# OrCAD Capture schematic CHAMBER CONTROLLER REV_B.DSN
size C; title: chamber controller; rev: B
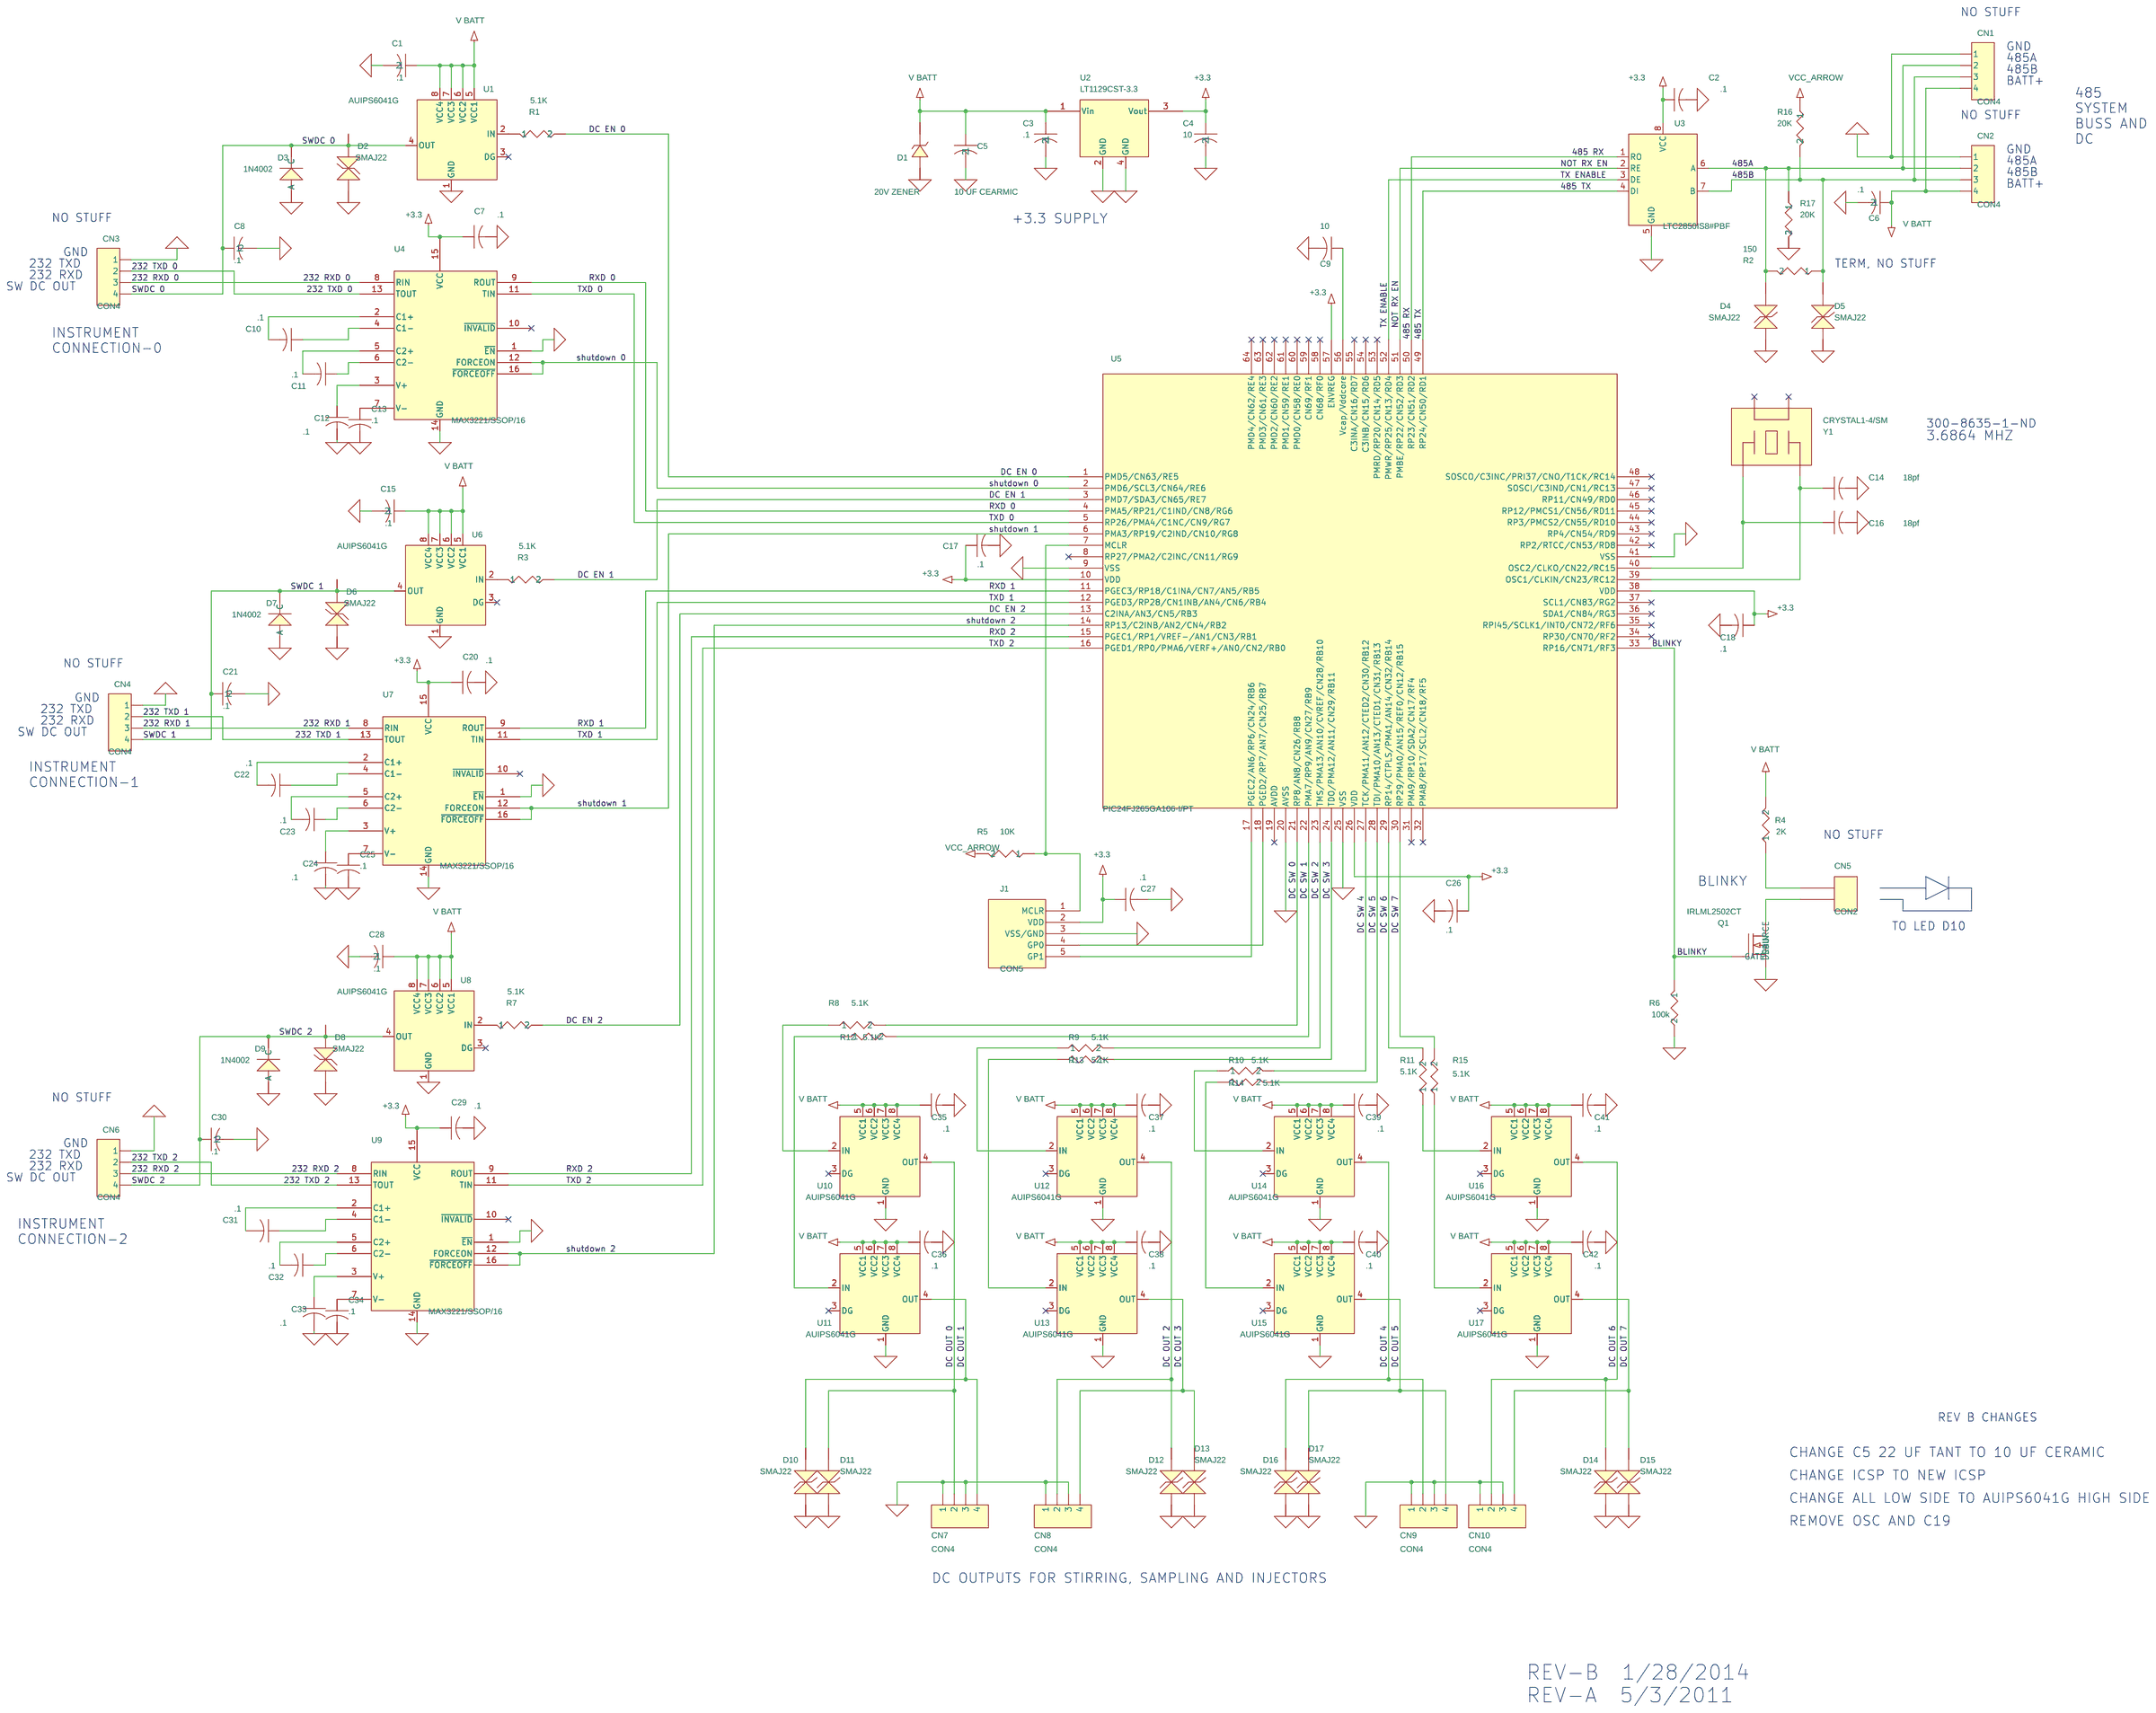
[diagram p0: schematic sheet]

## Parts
C1  .1  [SM/C_0805]
C2  .1  [SM/C_0805]
C3  .1  [SM/C_0805]
C4  10  [SM/C_1210]
C5  10 UF CEARMIC  [SM/CT_7343_12]
C6  .1  [SM/C_0805]
C7  .1  [SM/C_0805]
C8  .1  [SM/C_0805]
C9  10  [SM/C_0805]
C10  .1  [SM/C_0805]
C11  .1  [SM/C_0805]
C12  .1  [SM/C_0805]
C13  .1  [SM/C_0805]
C14  18pf  [SM/C_0805]
C15  .1  [SM/C_0805]
C16  18pf  [SM/C_0805]
C17  .1  [SM/C_0805]
C18  .1  [SM/C_0805]
C20  .1  [SM/C_0805]
C21  .1  [SM/C_0805]
C22  .1  [SM/C_0805]
C23  .1  [SM/C_0805]
C24  .1  [SM/C_0805]
C25  .1  [SM/C_0805]
C26  .1  [SM/C_0805]
C27  .1  [SM/C_0805]
C28  .1  [SM/C_0805]
C29  .1  [SM/C_0805]
C30  .1  [SM/C_0805]
C31  .1  [SM/C_0805]
C32  .1  [SM/C_0805]
C33  .1  [SM/C_0805]
C34  .1  [SM/C_0805]
C35  .1  [SM/C_0805]
C36  .1  [SM/C_0805]
C37  .1  [SM/C_0805]
C38  .1  [SM/C_0805]
C39  .1  [SM/C_0805]
C40  .1  [SM/C_0805]
C41  .1  [SM/C_0805]
C42  .1  [SM/C_0805]
CN1  CON4  [BLKCON.156/VH/TM1SQS/W.156/4]
CN2  CON4  [BLKCON.156/VH/TM1SQS/W.156/4]
CN3  CON4  [BLKCON.156/VH/TM1SQS/W.156/4]
CN4  CON4  [BLKCON.156/VH/TM1SQS/W.156/4]
CN5  CON2  [BLKCON.156/VH/TM1SQS/W.156/2]
CN6  CON4  [BLKCON.156/VH/TM1SQS/W.156/4]
CN7  CON4  [BLKCON.156/VH/TM1SQS/W.156/4]
CN8  CON4  [BLKCON.156/VH/TM1SQS/W.156/4]
CN9  CON4  [BLKCON.156/VH/TM1SQS/W.156/4]
CN10  CON4  [BLKCON.156/VH/TM1SQS/W.156/4]
D1  20V ZENER  [SM/DO213AB_12]
D2  SMAJ22  [SM/R_2010]
D3  1N4002  [SM/D_MLL41]
D4  SMAJ22  [SM/R_2010]
D5  SMAJ22  [SM/R_2010]
D6  SMAJ22  [SM/R_2010]
D7  1N4002  [SM/D_MLL41]
D8  SMAJ22  [SM/R_2010]
D9  1N4002  [SM/D_MLL41]
D10  SMAJ22  [SM/R_2010]
D11  SMAJ22  [SM/R_2010]
D12  SMAJ22  [SM/R_2010]
D13  SMAJ22  [SM/R_2010]
D14  SMAJ22  [SM/R_2010]
D15  SMAJ22  [SM/R_2010]
D16  SMAJ22  [SM/R_2010]
D17  SMAJ22  [SM/R_2010]
J1  CON5  [BLKCON.100/VH/TM1SQS/W.100/5]
Q1  IRLML2502CT  [SM/SOT23_123]
R1  5.1K  [SM/C_0805]
R2  150  [SM/C_0805]
R3  5.1K  [SM/C_0805]
R4  2K  [SM/C_0805]
R5  10K  [SM/C_0805]
R6  100k  [SM/C_0805]
R7  5.1K  [SM/C_0805]
R8  5.1K  [SM/C_0805]
R9  5.1K  [SM/C_0805]
R10  5.1K  [SM/C_0805]
R11  5.1K  [SM/C_0805]
R12  5.1K  [SM/C_0805]
R13  5.1K  [SM/C_0805]
R14  5.1K  [SM/C_0805]
R15  5.1K  [SM/C_0805]
R16  20K  [SM/C_0805]
R17  20K  [SM/C_0805]
U1  AUIPS6041G  [SOG.050/8/WG.244/L.175]
U2  LT1129CST-3.3  [SM/SOT223_1234]
U3  LTC2850IS8#PBF  [SOG.050/8/WG.244/L.200]
U4  MAX3221/SSOP/16  [SOG.65M/16/WG8.20/L6.35]
U5  PIC24FJ265GA106-I/PT  [QUAD.50M/64/WG11]
U6  AUIPS6041G  [SOG.050/8/WG.244/L.175]
U7  MAX3221/SSOP/16  [SOG.65M/16/WG8.20/L6.35]
U8  AUIPS6041G  [SOG.050/8/WG.244/L.175]
U9  MAX3221/SSOP/16  [SOG.65M/16/WG8.20/L6.35]
U10  AUIPS6041G  [SOG.050/8/WG.244/L.175]
U11  AUIPS6041G  [SOG.050/8/WG.244/L.175]
U12  AUIPS6041G  [SOG.050/8/WG.244/L.175]
U13  AUIPS6041G  [SOG.050/8/WG.244/L.175]
U14  AUIPS6041G  [SOG.050/8/WG.244/L.175]
U15  AUIPS6041G  [SOG.050/8/WG.244/L.175]
U16  AUIPS6041G  [SOG.050/8/WG.244/L.175]
U17  AUIPS6041G  [SOG.050/8/WG.244/L.175]
Y1  CRYSTAL1-4/SM  [SMXTAL_2]

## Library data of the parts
C1 = CAP
C2 C7 C9-C14 C16-C18 C20 C22-C27 C29 C31-C42 = CAPACITOR
C3 = CAP_8
C4 = CAP_6
C5 = CAP_2
C6 = CAP_3
C8 = CAP_5
C15 = CAP_7
C21 = CAP_9
C28 = CAP_4
C30 = CAP_1
CN1 = CON4_7
CN2 = CON4_4
CN3 = CON4
CN4 = CON4_3
CN5 = CON2
CN6 = CON4_6
CN7 = CON4_2
CN8 = CON4_8
CN9 = CON4_5
CN10 = CON4_1
D1 = DIODE_ZENER_0
D2 D4-D6 D8 D10-D17 = TRANZORB_1
D3 = DIODE_0_2
D7 = DIODE_0
D9 = DIODE_0_1
J1 = CON5_0
Q1 = MOSFET_N_1
R1 = RESISTOR_16
R2 = RESISTOR_3
R3 = RESISTOR_14
R4 = RESISTOR_13
R5 = RESISTOR_9
R6 = RESISTOR_15
R7 = RESISTOR_10
R8 = RESISTOR_5
R9 = RESISTOR
R10 = RESISTOR_6
R11 = RESISTOR_2
R12 = RESISTOR_7
R13 = RESISTOR_1
R14 = RESISTOR_12
R15 = RESISTOR_8
R16 = RESISTOR_4
R17 = RESISTOR_11
U1 U6 U8 U10-U17 = IPS6041GPbF_0
U2 = 78XX_SM_0
U3 = SN65LVDS179_SO_2
U4 U7 U9 = MAX3221_SO_0
U5 = PIC24FJ256GA110_0
Y1 = CRYSTAL1-4_SM_0

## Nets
GND_SIGNAL: C1.2 C2.2 C3.2 C4.2 C5.2 C6.2 C7.2 C8.2 C9.2 C12.2 C13.2 C14.2 C15.2 C16.2 C17.2 C18.2 C20.2 C21.2 C24.2 C25.2 C26.2 C27.2 C28.2 C29.2 C30.2 C33.2 C34.2 C35.2 C36.2 C37.2 C38.2 C39.2 C40.2 C41.2 C42.2 CN1.1 CN2.1 CN3.1 CN4.1 CN6.1 CN7.1 CN7.3 CN8.1 CN8.3 CN9.1 CN9.3 CN10.1 CN10.3 D1.2(ANODE) D2.1 D3.A D4.1 D5.1 D6.1 D7.A D8.1 D9.A D10.1 D11.1 D12.1 D13.1 D14.1 D15.1 D16.1 D17.1 J1.3(VSS/GND) Q1.2(SOURCE) R6.2 R17.2 U1.1(GND) U2.2(GND) U2.4(GND) U3.5(GND) U4.1(~{EN}) U4.14(GND) U5.9(VSS) U5.20(AVSS) U5.25(VSS) U5.41(VSS) U6.1(GND) U7.1(~{EN}) U7.14(GND) U8.1(GND) U9.1(~{EN}) U9.14(GND) U10.1(GND) U11.1(GND) U12.1(GND) U13.1(GND) U14.1(GND) U15.1(GND) U16.1(GND) U17.1(GND)
232 RXD 0: CN3.3 U4.8(RIN)
232 RXD 1: CN4.3 U7.8(RIN)
232 RXD 2: CN6.3 U9.8(RIN)
232 TXD 0: CN3.2 U4.13(TOUT)
232 TXD 1: CN4.2 U7.13(TOUT)
232 TXD 2: CN6.2 U9.13(TOUT)
485 RX: U3.1(RO) U5.50(RP23/CN51/RD2)
485 TX: U3.4(DI) U5.49(RP24/CN50/RD1)
485A: CN1.2 CN2.2 D4.2 R2.2 R17.1 U3.6(A)
485B: CN1.3 CN2.3 D5.2 R2.1 R16.2 U3.7(B)
+3.3: C2.1 C4.1 C7.1 C17.1 C18.1 C20.1 C26.1 C27.1 C29.1 J1.2(VDD) R5.2 R16.1 U2.3(Vout) U3.8(VCC) U4.15(VCC) U5.10(VDD) U5.26(VDD) U5.38(VDD) U5.57(ENVREG) U7.15(VCC) U9.15(VCC)
BLINKY: Q1.1(GATE) R6.1 U5.33(RP16/CN71/RF3)
DC EN 0: R1.2 U5.1(PMD5/CN63/RE5)
DC EN 1: R3.2 U5.3(PMD7/SDA3/CN65/RE7)
DC EN 2: R7.2 U5.13(C2INA/AN3/CN5/RB3)
DC OUT 0: CN7.2 D11.2 U10.4(OUT)
DC OUT 1: CN7.4 D10.2 U11.4(OUT)
DC OUT 2: CN8.2 D12.2 U12.4(OUT)
DC OUT 3: CN8.4 D13.2 U13.4(OUT)
DC OUT 4: CN9.2 D16.2 U14.4(OUT)
DC OUT 5: CN9.4 D17.2 U15.4(OUT)
DC OUT 6: CN10.2 D14.2 U16.4(OUT)
DC OUT 7: CN10.4 D15.2 U17.4(OUT)
DC SW 0: R8.2 U5.21(RP8/AN8/CN26/RB8)
DC SW 1: R12.2 U5.22(PMA7/RP9/AN9/CN27/RB9)
DC SW 2: R9.2 U5.23(TMS/PMA13/AN10/CVREF/CN28/RB10)
DC SW 3: R13.2 U5.24(TDO/PMA12/AN11/CN29/RB11)
DC SW 4: R10.2 U5.27(TCK/PMA11/AN12/CTED2/CN30/RB12)
DC SW 5: R14.2 U5.28(TDI/PMA10/AN13/CTED1/CN31/RB13)
DC SW 6: R11.2 U5.29(RP14/CTPLS/PMA1/AN14/CN32/RB14)
DC SW 7: R15.2 U5.30(RP29/PMA0/AN15/REF0/CN12/RB15)
NOT RX EN: U3.2(RE) U5.51(PMBE/RP22/CN52/RD3)
RXD 0: U4.9(ROUT) U5.4(PMA5/RP21/C1IND/CN8/RG6)
RXD 1: U5.11(PGEC3/RP18/C1INA/CN7/AN5/RB5) U7.9(ROUT)
RXD 2: U5.15(PGEC1/RP1/VREF-/AN1/CN3/RB1) U9.9(ROUT)
shutdown 0: U4.12(FORCEON) U4.16(~{FORCEOFF}) U5.2(PMD6/SCL3/CN64/RE6)
shutdown 1: U5.6(PMA3/RP19/C2IND/CN10/RG8) U7.12(FORCEON) U7.16(~{FORCEOFF})
shutdown 2: U5.14(RP13/C2INB/AN2/CN4/RB2) U9.12(FORCEON) U9.16(~{FORCEOFF})
SWDC 0: C8.1 CN3.4 D2.2 D3.C U1.4(OUT)
SWDC 1: C21.1 CN4.4 D6.2 D7.C U6.4(OUT)
SWDC 2: C30.1 CN6.4 D8.2 D9.C U8.4(OUT)
TX ENABLE: U3.3(DE) U5.52(PMWR/RP25/CN13/RD4)
TXD 0: U4.11(TIN) U5.5(RP26/PMA4/C1NC/CN9/RG7)
TXD 1: U5.12(PGED3/RP28/CN1INB/AN4/CN6/RB4) U7.11(TIN)
TXD 2: U5.16(PGED1/RP0/PMA6/VERF+/AN0/CN2/RB0) U9.11(TIN)
V Batt: C1.1 C3.1 C5.1 C6.1 C15.1 C28.1 C35.1 C36.1 C37.1 C38.1 C39.1 C40.1 C41.1 C42.1 CN1.4 CN2.4 D1.1(CATHODE) R4.2 U1.5(VCC1) U1.6(VCC2) U1.7(VCC3) U1.8(VCC4) U2.1(Vin) U6.5(VCC1) U6.6(VCC2) U6.7(VCC3) U6.8(VCC4) U8.5(VCC1) U8.6(VCC2) U8.7(VCC3) U8.8(VCC4) U10.5(VCC1) U10.6(VCC2) U10.7(VCC3) U10.8(VCC4) U11.5(VCC1) U11.6(VCC2) U11.7(VCC3) U11.8(VCC4) U12.5(VCC1) U12.6(VCC2) U12.7(VCC3) U12.8(VCC4) U13.5(VCC1) U13.6(VCC2) U13.7(VCC3) U13.8(VCC4) U14.5(VCC1) U14.6(VCC2) U14.7(VCC3) U14.8(VCC4) U15.5(VCC1) U15.6(VCC2) U15.7(VCC3) U15.8(VCC4) U16.5(VCC1) U16.6(VCC2) U16.7(VCC3) U16.8(VCC4) U17.5(VCC1) U17.6(VCC2) U17.7(VCC3) U17.8(VCC4)
N1317258: C10.2 U4.2(C1+)
N1317370: C10.1 U4.4(C1-)
N1317469: C11.2 U4.5(C2+)
N1317517: C11.1 U4.6(C2-)
N1317901: C12.1 U4.3(V+)
N2111308: C22.2 U7.2(C1+)
N2111364: C22.1 U7.4(C1-)
N2111372: C23.2 U7.5(C2+)
N2111400: C23.1 U7.6(C2-)
N2111444: C24.1 U7.3(V+)
N2114655: C31.2 U9.2(C1+)
N2114715: C31.1 U9.4(C1-)
N2114723: C32.2 U9.5(C2+)
N2114727: C32.1 U9.6(C2-)
N2114795: C33.1 U9.3(V+)
N2131395: J1.4(GP0) U5.18(PGED2/RP7/AN7/CN25/RB7)
N2131565: J1.5(GP1) U5.17(PGEC2/AN6/RP6/CN24/RB6)
N2131735: J1.1(MCLR) R5.1 U5.7(MCLR)
N2219388: C9.1 U5.56(Vcap/Vddcore)
N2260858: C16.1 U5.40(OSC2/CLKO/CN22/RC15) Y1.1
N2261038: C14.1 U5.39(OSC1/CLKIN/CN23/RC12) Y1.4
N2278731: CN5.1 R4.1
N2278761: CN5.2 Q1.3(DRAIN)
N2306648: R8.1 U10.2(IN)
N2306660: R12.1 U11.2(IN)
N2312593: R9.1 U12.2(IN)
N2312597: R13.1 U13.2(IN)
N2313908: R10.1 U14.2(IN)
N2313912: R14.1 U15.2(IN)
N2314036: R11.1 U16.2(IN)
N2314040: R15.1 U17.2(IN)
N2335801: R3.1 U6.2(IN)
N2335802: C25.1 U7.7(V-)
N2335804: C34.1 U9.7(V-)
N2335806: R1.1 U1.2(IN)
N2335808: R7.1 U8.2(IN)
N2335825: C13.1 U4.7(V-)

Not connected (* = marked no-connect by the designer): U1 3(DG)*; U4 10(~{INVALID})*; U5 8(RP27/PMA2/C2INC/CN11/RG9)* 19(AVDD)* 31(PMA9/RP10/SDA2/CN17/RF4)* 32(PMA8/RP17/SCL2/CN18/RF5)* 34(RP30/CN70/RF2)* 35(RPI45/SCLK1/INT0/CN72/RF6)* 36(SDA1/CN84/RG3)* 37(SCL1/CN83/RG2)* 42(RP2/RTCC/CN53/RD8)* 43(RP4/CN54/RD9)* 44(RP3/PMCS2/CN55/RD10)* 45(RP12/PMCS1/CN56/RD11)* 46(RP11/CN49/RD0)* 47(SOSCI/C3IND/CN1/RC13)* 48(SOSCO/C3INC/PRI37/CNO/T1CK/RC14)* 53(PMRD/RP20/CN14/RD5)* 54(C3INB/CN15/RD6)* 55(C3INA/CN16/RD7)* 58(CN68/RF0)* 59(CN69/RF1)* 60(PMD0/CN58/RE0)* 61(PMD1/CN59/RE1)* 62(PMD2/CN60/RE2)* 63(PMD3/CN61/RE3)* 64(PMD4/CN62/RE4)*; U6 3(DG)*; U7 10(~{INVALID})*; U8 3(DG)*; U9 10(~{INVALID})*; U10 3(DG)*; U11 3(DG)*; U12 3(DG)*; U13 3(DG)*; U14 3(DG)*; U15 3(DG)*; U16 3(DG)*; U17 3(DG)*; Y1 2* 3*

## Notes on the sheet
- NO STUFF
- 485A
- GND
- 485B
- BATT+
- 485
  SYSTEM
  BUSS AND
  DC
- NO STUFF
- GND
- 485A
- 485B
- BATT+
- NO STUFF
- +3.3 SUPPLY
- GND
- 232 TXD
- TERM, NO STUFF
- SW DC OUT
- 232 RXD
- INSTRUMENT
  CONNECTION-0
- 3.6864 MHZ
- 300-8635-1-ND
- NO STUFF
- GND
- 232 TXD
- SW DC OUT
- 232 RXD
- INSTRUMENT
  CONNECTION-1
- NO STUFF
- BLINKY
- TO LED D10
- NO STUFF
- GND
- 232 TXD
- SW DC OUT
- 232 RXD
- INSTRUMENT
  CONNECTION-2
- REV B CHANGES
- CHANGE C5 22 UF TANT TO 10 UF CERAMIC
- CHANGE ICSP TO NEW ICSP
- CHANGE ALL LOW SIDE TO AUIPS6041G HIGH SIDE
- REMOVE OSC AND C19
- DC OUTPUTS FOR STIRRING, SAMPLING AND INJECTORS
- REV-B  1/28/2014
- REV-A  5/3/2011
